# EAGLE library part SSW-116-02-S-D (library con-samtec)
THROUGH-HOLE .025" SQ POST SOCKET Source: Samtec SSW.pdf
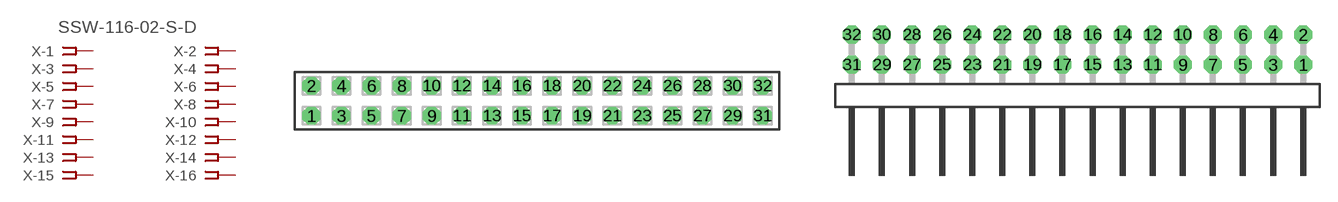
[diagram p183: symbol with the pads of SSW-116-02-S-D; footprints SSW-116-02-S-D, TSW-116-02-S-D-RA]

Designator prefix X; gates -1=FPINV -2=FPIN -3=FPIN -4=FPIN -5=FPIN -6=FPIN -7=FPIN -8=FPIN -9=FPIN -10=FPIN -11=FPIN -12=FPIN -13=FPIN -14=FPIN -15=FPIN -16=FPIN -17=FPIN -18=FPIN -19=FPIN -20=FPIN -21=FPIN -22=FPIN -23=FPIN -24=FPIN -25=FPIN -26=FPIN -27=FPIN -28=FPIN -29=FPIN -30=FPIN -31=FPIN -32=FPIN

## SSW-116-02-S-D (MPN: SSW-116-02-S-D; OC_FARNELL: unknown; OC_NEWARK: 11P9577)  [SSW-116-02-S-D]
1  -1:1  pas
2  -2:1  pas
3  -3:1  pas
4  -4:1  pas
5  -5:1  pas
6  -6:1  pas
7  -7:1  pas
8  -8:1  pas
9  -9:1  pas
10  -10:1  pas
11  -11:1  pas
12  -12:1  pas
13  -13:1  pas
14  -14:1  pas
15  -15:1  pas
16  -16:1  pas
17  -17:1  pas
18  -18:1  pas
19  -19:1  pas
20  -20:1  pas
21  -21:1  pas
22  -22:1  pas
23  -23:1  pas
24  -24:1  pas
25  -25:1  pas
26  -26:1  pas
27  -27:1  pas
28  -28:1  pas
29  -29:1  pas
30  -30:1  pas
31  -31:1  pas
32  -32:1  pas

## SSW-116-02-S-D-RA (MPN: SSW-116-02-S-D-RA; OC_FARNELL: unknown; OC_NEWARK: 11P9578)  [TSW-116-02-S-D-RA]
Pads as for SSW-116-02-S-D

## Footprint SSW-116-02-S-D (pad centres in mm)
THROUGH-HOLE .025" SQ POST SOCKET Source: Samtec SSW.pdf
drill 1 pad 1.5 octagon: 1 -19.05,-1.27; 2 -19.05,1.27; 3 -16.51,-1.27; 4 -16.51,1.27; 5 -13.97,-1.27; 6 -13.97,1.27; 7 -11.43,-1.27; 8 -11.43,1.27; 9 -8.89,-1.27; 10 -8.89,1.27; 11 -6.35,-1.27; 12 -6.35,1.27; 13 -3.81,-1.27; 14 -3.81,1.27; 15 -1.27,-1.27; 16 -1.27,1.27; 17 1.27,-1.27; 18 1.27,1.27; 19 3.81,-1.27; 20 3.81,1.27; 21 6.35,-1.27; 22 6.35,1.27; 23 8.89,-1.27; 24 8.89,1.27; 25 11.43,-1.27; 26 11.43,1.27; 27 13.97,-1.27; 28 13.97,1.27; 29 16.51,-1.27; 30 16.51,1.27; 31 19.05,-1.27; 32 19.05,1.27

## Footprint TSW-116-02-S-D-RA (pad centres in mm)
THROUGH-HOLE .025" SQ POST HEADER Source: Samtec TSW.pdf
drill 1 pad 1.5 octagon: 1 19.05,1.524; 2 19.05,4.064; 3 16.51,1.524; 4 16.51,4.064; 5 13.97,1.524; 6 13.97,4.064; 7 11.43,1.524; 8 11.43,4.064; 9 8.89,1.524; 10 8.89,4.064; 11 6.35,1.524; 12 6.35,4.064; 13 3.81,1.524; 14 3.81,4.064; 15 1.27,1.524; 16 1.27,4.064; 17 -1.27,1.524; 18 -1.27,4.064; 19 -3.81,1.524; 20 -3.81,4.064; 21 -6.35,1.524; 22 -6.35,4.064; 23 -8.89,1.524; 24 -8.89,4.064; 25 -11.43,1.524; 26 -11.43,4.064; 27 -13.97,1.524; 28 -13.97,4.064; 29 -16.51,1.524; 30 -16.51,4.064; 31 -19.05,1.524; 32 -19.05,4.064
